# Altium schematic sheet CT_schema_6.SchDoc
size 369 x 245 mm
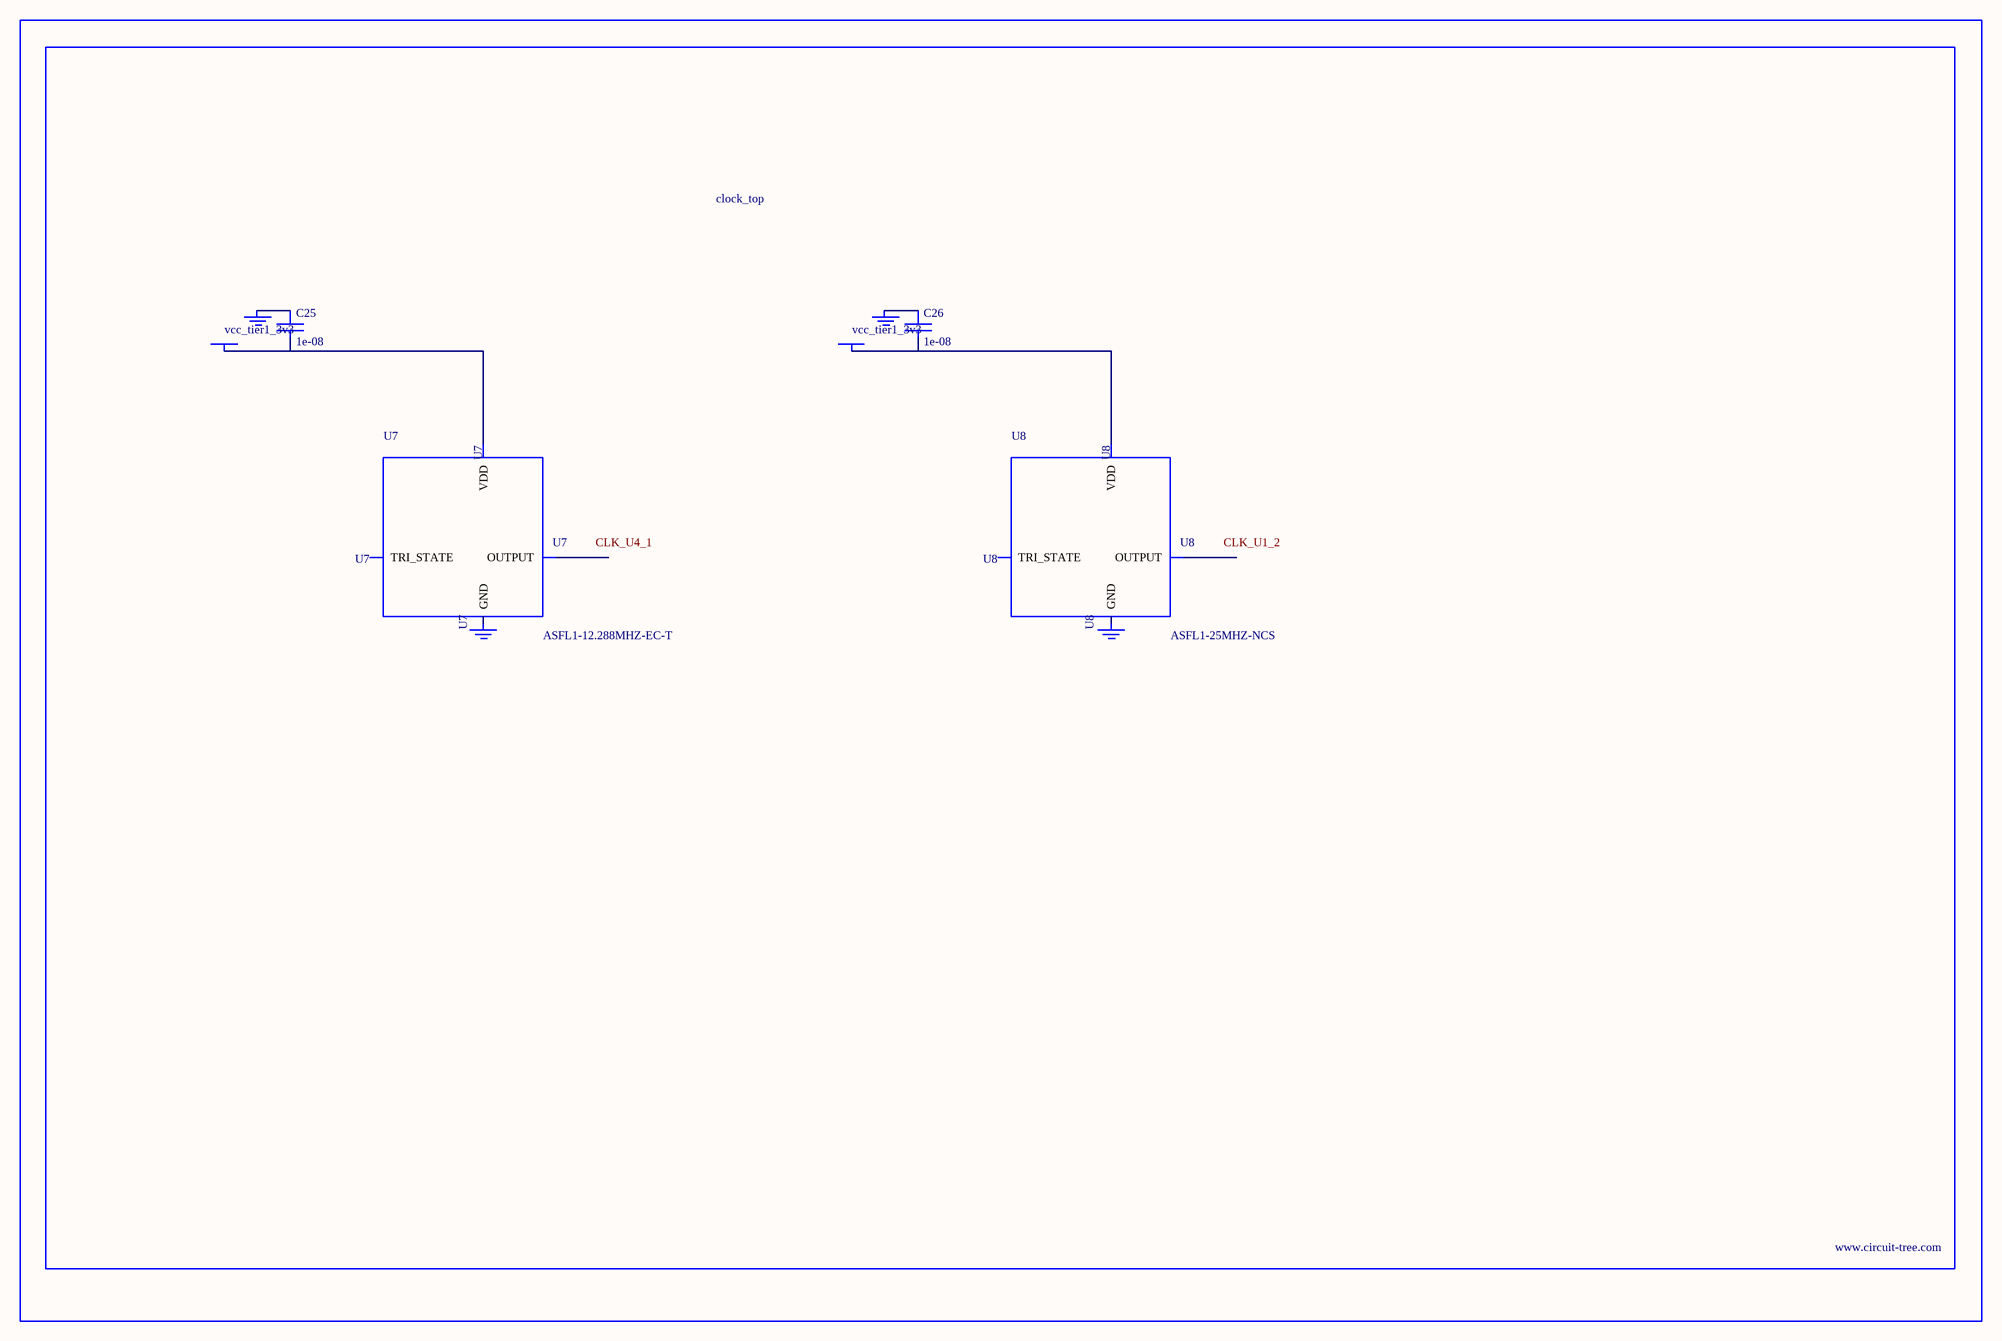
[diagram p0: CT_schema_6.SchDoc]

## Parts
BORDER5  (no value)
C25  1e-08  [C0402]
C26  1e-08  [C0402]
GND_INSTANCE_5_0  (no value)
GND_INSTANCE_5_1  (no value)
GND_INSTANCE_5_2  (no value)
GND_INSTANCE_5_3  (no value)
POWER_INSTANCE_5_0  vcc_tier1_3v3
POWER_INSTANCE_5_1  vcc_tier1_3v3
U7  ASFL1-12.288MHZ-EC-T  [ASFL1]
U8  ASFL1-25MHZ-NCS  [ASFL1]

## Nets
NetC25_1: C25.1 GND_INSTANCE_5_0.0(GND)
NetC25_2: C25.2 POWER_INSTANCE_5_0.0(PWR) U7.4(VDD)
NetC26_1: C26.1 GND_INSTANCE_5_2.0(GND)
NetC26_2: C26.2 POWER_INSTANCE_5_1.0(PWR) U8.4(VDD)

Not connected (* = marked no-connect by the designer): GND_INSTANCE_5_1 0(GND); GND_INSTANCE_5_3 0(GND); U7 1(TRI_STATE) 2(GND) 3(OUTPUT); U8 1(TRI_STATE) 2(GND) 3(OUTPUT)

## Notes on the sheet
- Labels drawn without touching a wire or pin: CLK_U1_2, CLK_U4_1

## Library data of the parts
BORDER5 = BORDER_PAGE5
C25 C26 = C0402C103K3RAC
GND_INSTANCE_5_0-GND_INSTANCE_5_3 = GND
POWER_INSTANCE_5_0 POWER_INSTANCE_5_1 = PWR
